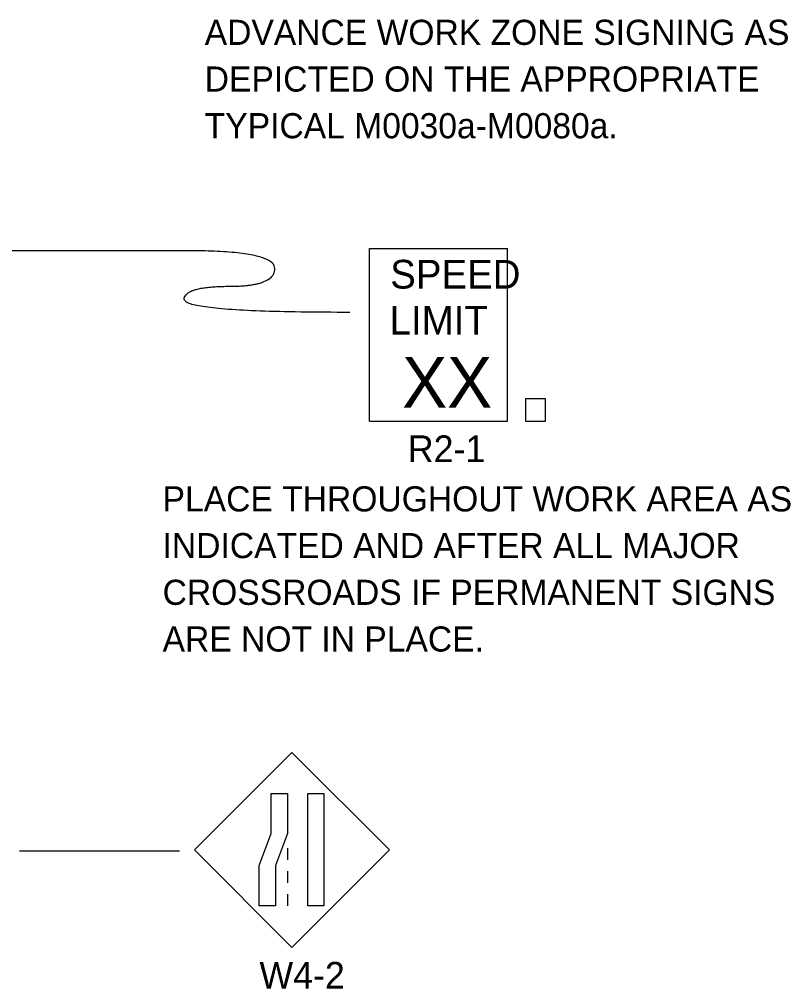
# Model space of a CAD drawing. Extents: x 16733 to 18475, y 7003 to 8205.
# Drawn here: x 17167.5 to 17382.2, y 7680.4 to 7950.3 of the extents above; entities that cross this region are included whole.
import ezdxf

# ---------------------------------------------------------------- set-up
doc = ezdxf.new("R2010")
doc.units = 0
doc.layers.add('TRAFFIC_SIGNS_PR', color=7, linetype='Continuous')
doc.layers.add('TYPICAL_TEXT_DIMEN_PR', color=7, linetype='Continuous')

msp = doc.modelspace()

# ---------------------------------------------------------------- linework, layer by layer
at = {"layer": 'TRAFFIC_SIGNS_PR'}
for p, q in [((17264.93, 7886.44), (17303.33, 7886.44)), ((17264.93, 7838.44), (17264.93, 7886.44)), ((17303.33, 7838.44), (17303.33, 7886.44)), ((17264.93, 7838.44), (17303.33, 7838.44)), ((17243.34, 7746.19), (17216.19, 7719.04)), ((17270.49, 7719.04), (17243.34, 7746.19)), ((17242.09, 7719.53), (17242.09, 7716.33)), ((17216.19, 7719.04), (17243.34, 7691.88)), ((17243.34, 7691.88), (17270.49, 7719.04)), ((17242.09, 7713.13), (17242.09, 7709.93)), ((17242.09, 7706.73), (17242.09, 7703.53))]:
    msp.add_line(p, q, dxfattribs=at)
for points in [[(17308.35, 7838.44), (17313.94, 7838.44), (17313.94, 7844.62), (17308.35, 7844.62)], [(17242.09, 7734.77), (17242.09, 7723.59), (17238.75, 7714.71), (17238.75, 7703.53), (17234.25, 7703.53), (17234.25, 7714.71), (17237.6, 7723.59), (17237.6, 7734.77)], [(17252.23, 7734.77), (17252.23, 7703.53), (17247.73, 7703.53), (17247.73, 7734.77)]]:
    msp.add_lwpolyline(points, close=True, dxfattribs=at)
at = {"layer": 'TYPICAL_TEXT_DIMEN_PR'}
msp.add_line((17212.07, 7718.7), (17167.52, 7718.7), dxfattribs=at)
msp.add_open_spline([(17259.5, 7868.68), (17213.41, 7868.68), (17213.41, 7875.95), (17238.58, 7875.95), (17238.58, 7885.85), (17188.94, 7885.85), (17148.43, 7885.85)], degree=2, dxfattribs=at)

# ---------------------------------------------------------------- texts
at = {"layer": 'TRAFFIC_SIGNS_PR'}
for s, height, p in [('ADVANCE WORK ZONE SIGNING AS', 7, (17219.06, 7943.15)), ('DEPICTED ON THE APPROPRIATE', 7, (17219.06, 7930.15)), ('TYPICAL M0030a-M0080a.', 7, (17219.06, 7917.15)), ('SPEED', 8, (17270.7, 7875.31)), ('LIMIT', 8, (17270.54, 7862.51)), ('XX', 14.031, (17274.04, 7842.2)), ('R2-1', 7.44, (17275.61, 7827)), ('PLACE THROUGHOUT WORK AREA AS', 7, (17207.33, 7813.27)), ('INDICATED AND AFTER ALL MAJOR', 7, (17207.33, 7800.27)), ('CROSSROADS IF PERMANENT SIGNS', 7, (17207.33, 7787.27)), ('ARE NOT IN PLACE.', 7, (17207.33, 7774.27)), ('W4-2', 7.44, (17234.3, 7680.44))]:
    msp.add_text(s, height=height, dxfattribs=at).set_placement(p)

doc.saveas('drawing.dxf')
